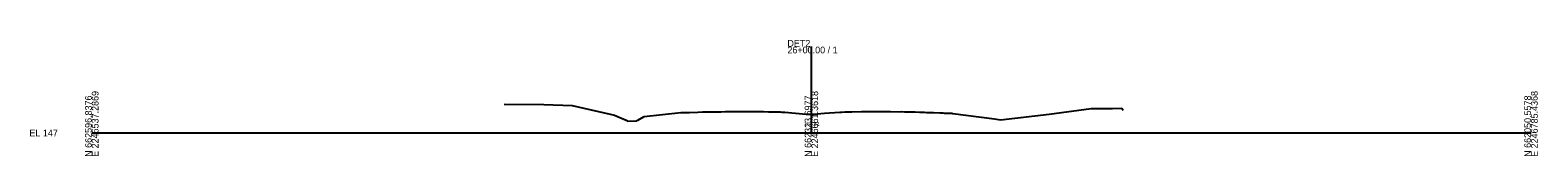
# Model space of a CAD drawing. Extents: x -26 to 603, y -10 to 9526.
# Drawn here: x -26 to 603, y 8990 to 9039 of the extents above; entities that cross this region are included whole.
import ezdxf

# ---------------------------------------------------------------- set-up
doc = ezdxf.new("R2010")
doc.units = 0
for name, color, linetype in [('Default', 7, 'Continuous'), ('Exist Cross Section Cell', 7, 'Continuous'), ('Exist XS Center Line Elevation Label', 7, 'Continuous'), ('Exist XS Ground Line', 7, 'Continuous')]:
    doc.layers.add(name, color=color, linetype=linetype)

msp = doc.modelspace()

# ---------------------------------------------------------------- linework, layer by layer
at = {"layer": 'Exist Cross Section Cell'}
for p, q in [((300, 9000), (300, 9035.96)), ((0, 9000), (300, 9000)), ((300, 9000), (600, 9000))]:
    msp.add_line(p, q, dxfattribs=at)
at = {"layer": 'Exist XS Ground Line'}
for p, q in [((171.87, 9011.99), (188.44, 9011.79)), ((188.44, 9011.79), (200.23, 9011.48)), ((200.23, 9011.48), (216.16, 9007.77)), ((216.16, 9007.77), (217.85, 9007.37)), ((217.85, 9007.37), (222.72, 9005.26)), ((227.59, 9005.25), (230.28, 9006.88)), ((230.28, 9006.88), (245.61, 9008.46)), ((245.61, 9008.46), (246.18, 9008.46)), ((246.18, 9008.46), (246.93, 9008.48)), ((246.93, 9008.48), (247.91, 9008.51)), ((247.91, 9008.51), (249.14, 9008.55)), ((249.14, 9008.55), (252.67, 9008.66)), ((252.67, 9008.66), (254.64, 9008.72)), ((254.64, 9008.72), (256.45, 9008.76)), ((256.45, 9008.76), (260.2, 9008.84)), ((260.2, 9008.84), (260.86, 9008.85)), ((260.86, 9008.85), (261.75, 9008.85)), ((261.75, 9008.85), (262.08, 9008.85)), ((262.08, 9008.85), (262.42, 9008.85)), ((262.42, 9008.85), (264, 9008.86)), ((264, 9008.86), (265.62, 9008.87)), ((265.62, 9008.87), (267.78, 9008.88)), ((267.78, 9008.88), (271.41, 9008.92)), ((271.41, 9008.92), (273.74, 9008.95)), ((273.74, 9008.95), (275.85, 9008.92)), ((275.85, 9008.92), (276.6, 9008.91)), ((276.6, 9008.91), (279.99, 9008.86)), ((279.99, 9008.86), (282.09, 9008.83)), ((282.09, 9008.83), (282.72, 9008.82)), ((282.72, 9008.82), (284.65, 9008.77)), ((284.65, 9008.77), (285.61, 9008.76)), ((285.61, 9008.76), (287.04, 9008.76)), ((287.04, 9008.76), (287.72, 9008.7)), ((287.72, 9008.7), (288.61, 9008.69)), ((288.61, 9008.69), (288.99, 9008.63)), ((288.99, 9008.63), (297.81, 9007.87)), ((297.81, 9007.87), (299.16, 9007.76)), ((299.16, 9007.76), (300, 9007.82)), ((300, 9007.82), (300.86, 9007.88)), ((300.86, 9007.88), (305.44, 9008.19)), ((305.44, 9008.19), (311.84, 9008.64)), ((311.84, 9008.64), (312.66, 9008.69)), ((312.66, 9008.69), (313.89, 9008.76)), ((313.89, 9008.76), (314.51, 9008.78)), ((314.51, 9008.78), (315.33, 9008.82)), ((315.33, 9008.82), (315.89, 9008.8)), ((315.89, 9008.8), (316.87, 9008.81)), ((316.87, 9008.81), (320.89, 9008.88)), ((320.89, 9008.88), (324.42, 9008.92)), ((324.42, 9008.92), (325.08, 9008.93)), ((325.08, 9008.93), (326.16, 9008.98)), ((326.16, 9008.98), (326.7, 9008.99)), ((326.7, 9008.99), (331.09, 9008.91)), ((331.09, 9008.91), (331.52, 9008.9)), ((331.52, 9008.9), (331.97, 9008.89)), ((331.97, 9008.89), (332.98, 9008.88)), ((332.98, 9008.88), (337.01, 9008.85)), ((337.01, 9008.85), (337.7, 9008.86)), ((337.7, 9008.86), (338.74, 9008.85)), ((338.74, 9008.85), (339.66, 9008.85)), ((339.66, 9008.85), (340.15, 9008.82)), ((340.15, 9008.82), (340.47, 9008.82)), ((340.47, 9008.82), (340.92, 9008.8)), ((340.92, 9008.8), (342.5, 9008.75)), ((342.5, 9008.75), (343.3, 9008.72)), ((343.3, 9008.72), (345.07, 9008.66)), ((345.07, 9008.66), (347.08, 9008.59)), ((347.08, 9008.59), (347.99, 9008.56)), ((347.99, 9008.56), (350.86, 9008.45)), ((350.86, 9008.45), (353.49, 9008.34)), ((353.49, 9008.34), (354.12, 9008.33)), ((354.12, 9008.33), (354.82, 9008.33)), ((354.82, 9008.33), (355.41, 9008.28)), ((355.41, 9008.28), (356.4, 9008.23)), ((356.4, 9008.23), (356.74, 9008.21)), ((356.74, 9008.21), (358.03, 9008.17)), ((358.03, 9008.17), (358.5, 9008.2)), ((358.5, 9008.2), (358.98, 9008.14)), ((358.98, 9008.14), (364.31, 9007.39)), ((364.31, 9007.39), (376.32, 9005.82)), ((378.81, 9005.45), (399.13, 9007.87)), ((399.13, 9007.87), (416.62, 9010.18)), ((416.62, 9010.18), (425.54, 9010.21)), ((425.54, 9010.21), (429.41, 9010.25)), ((429.41, 9010.25), (429.93, 9009.42)), ((222.72, 9005.26), (223.39, 9004.93)), ((223.39, 9004.93), (226.76, 9004.98)), ((226.76, 9004.98), (227.26, 9005.01)), ((227.26, 9005.01), (227.59, 9005.25)), ((376.32, 9005.82), (378.81, 9005.45))]:
    msp.add_line(p, q, dxfattribs=at)

# ---------------------------------------------------------------- texts
at = {"layer": 'Default'}
msp.add_text('-', height=0.0001, dxfattribs=at).set_placement((0, 9000))
msp.add_text('-', height=0.0001, dxfattribs=at).set_placement((0, 9000))
at = {"layer": 'Exist Cross Section Cell'}
for s, p in [('DET2', (290, 9035.96)), ('26+00.00 / 1', (290, 9033.16)), ('EL 147', (-26, 8998.6))]:
    msp.add_text(s, height=2.8, dxfattribs=at).set_placement(p)
for s, p in [('N 662596.8376', (0, 8990)), ('E 2246537.2869', (2.8, 8990)), ('N 662323.6977', (300, 8990)), ('E 2246661.3618', (302.8, 8990)), ('N 662050.5578', (600, 8990)), ('E 2246785.4368', (602.8, 8990))]:
    msp.add_text(s, height=2.8, rotation=90, dxfattribs=at).set_placement(p)
at = {"layer": 'Exist XS Center Line Elevation Label'}
msp.add_text('154.82', height=1.5, dxfattribs=at).set_placement((297.02, 9003.07))

doc.saveas('drawing.dxf')
